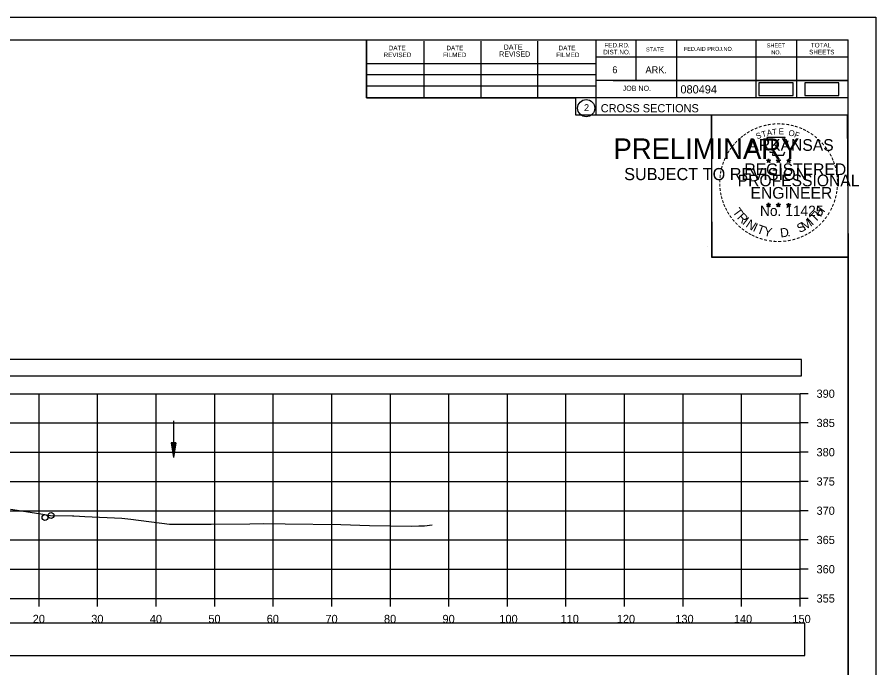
# Model space of a CAD drawing. Extents: x 1376273 to 1384221, y 378927 to 384592.
# Drawn here: x 1378240.7 to 1378387.4, y 379787.3 to 379898.5 of the extents above; entities that cross this region are included whole.
import ezdxf

# ---------------------------------------------------------------- set-up
doc = ezdxf.new("R2010")
doc.units = 0
for name, color, linetype in [('R_Axis', 7, 'Continuous'), ('R_Axis Annot', 7, 'Continuous'), ('R_Border', 7, 'Continuous'), ('R_Border PE', 7, 'Continuous'), ('R_Border Prem', 7, 'Continuous'), ('R_Drive', 7, 'Continuous'), ('R_Exist Surface', 7, 'Continuous'), ('R_Grid', 7, 'Continuous'), ('R_No Plot', 7, 'Continuous'), ('R_Water', 7, 'Continuous')]:
    doc.layers.add(name, color=color, linetype=linetype)

msp = doc.modelspace()

# ---------------------------------------------------------------- linework, layer by layer
at = {"layer": 'R_Axis'}
for p, q in [((1378374.46, 379799.14), (1378374.46, 379834.14)), ((1378375.86, 379834.14), (1378374.46, 379834.14)), ((1378375.86, 379829.14), (1378374.46, 379829.14)), ((1378375.86, 379824.14), (1378374.46, 379824.14)), ((1378375.86, 379819.14), (1378374.46, 379819.14)), ((1378375.86, 379814.14), (1378374.46, 379814.14)), ((1378375.86, 379809.14), (1378374.46, 379809.14)), ((1378375.86, 379804.14), (1378374.46, 379804.14)), ((1378074.46, 379799.14), (1378374.46, 379799.14)), ((1378244.46, 379797.74), (1378244.46, 379799.14)), ((1378254.46, 379797.74), (1378254.46, 379799.14)), ((1378264.46, 379797.74), (1378264.46, 379799.14)), ((1378274.46, 379797.74), (1378274.46, 379799.14)), ((1378284.46, 379797.74), (1378284.46, 379799.14)), ((1378294.46, 379797.74), (1378294.46, 379799.14)), ((1378304.46, 379797.74), (1378304.46, 379799.14)), ((1378314.46, 379797.74), (1378314.46, 379799.14)), ((1378324.46, 379797.74), (1378324.46, 379799.14)), ((1378334.46, 379797.74), (1378334.46, 379799.14)), ((1378344.46, 379797.74), (1378344.46, 379799.14)), ((1378354.46, 379797.74), (1378354.46, 379799.14)), ((1378364.46, 379797.74), (1378364.46, 379799.14)), ((1378374.46, 379797.74), (1378374.46, 379799.14)), ((1378375.86, 379799.14), (1378374.46, 379799.14))]:
    msp.add_line(p, q, dxfattribs=at)
at = {"layer": 'R_Axis Annot'}
for points in [[(1378072.9, 379837.19), (1378374.7, 379837.19), (1378374.7, 379840.01), (1378072.9, 379840.01)], [(1378073.48, 379789.42), (1378375.28, 379789.42), (1378375.28, 379794.94), (1378073.48, 379794.94)]]:
    msp.add_lwpolyline(points, close=True, dxfattribs=at)
at = {"layer": 'R_Border'}
for p, q in [((1378066.46, 379894.6), (1378382.64, 379894.6)), ((1378300.38, 379884.72), (1378300.38, 379894.6)), ((1378310.24, 379884.72), (1378310.24, 379894.4)), ((1378320, 379884.72), (1378320, 379894.4)), ((1378329.68, 379884.72), (1378329.68, 379894.4)), ((1378339.54, 379894.6), (1378339.54, 379881.8)), ((1378346.38, 379894.6), (1378346.38, 379887.66)), ((1378353.32, 379894.6), (1378353.32, 379884.72)), ((1378366.9, 379894.6), (1378366.9, 379884.72)), ((1378373.84, 379894.6), (1378373.84, 379884.72)), ((1378382.64, 379689.14), (1378382.64, 379894.6)), ((1378382.64, 379891.66), (1378339.54, 379891.66)), ((1378382.64, 379891.68), (1378382.64, 379891.68)), ((1378300.38, 379890.58), (1378339.54, 379890.58)), ((1378300.38, 379888.72), (1378339.54, 379888.72)), ((1378300.38, 379884.72), (1378300.38, 379886.78)), ((1378300.38, 379886.78), (1378339.54, 379886.78)), ((1378382.64, 379887.66), (1378339.54, 379887.66)), ((1378342.5, 379887.66), (1378382.64, 379887.66)), ((1378382.64, 379884.72), (1378300.38, 379884.72)), ((1378339.54, 379881.8), (1378382.64, 379881.8))]:
    msp.add_line(p, q, dxfattribs=at)
msp.add_circle((1378337.92, 379882.94), 1.47, dxfattribs=at)
at = {"layer": 'R_Border PE'}
for p, q in [((1378368.72, 379874.06), (1378369.07, 379873.95)), ((1378368.72, 379874.06), (1378368.98, 379874.01)), ((1378368.72, 379874.06), (1378368.96, 379873.94)), ((1378368.86, 379873.65), (1378369.07, 379873.95)), ((1378368.86, 379873.65), (1378368.98, 379873.89)), ((1378368.86, 379873.65), (1378369.07, 379873.87)), ((1378369.07, 379874.31), (1378369.03, 379874.06)), ((1378369.07, 379873.95), (1378369.07, 379874.31)), ((1378369.07, 379874.31), (1378369.12, 379874.06)), ((1378369.42, 379874.06), (1378369.07, 379873.95)), ((1378369.28, 379873.65), (1378369.07, 379873.95)), ((1378369.28, 379873.65), (1378369.07, 379873.86)), ((1378369.42, 379874.06), (1378369.13, 379874.01)), ((1378369.28, 379873.65), (1378369.15, 379873.94)), ((1378369.42, 379874.06), (1378369.21, 379873.96)), ((1378370.39, 379874.06), (1378370.74, 379873.95)), ((1378370.39, 379874.06), (1378370.65, 379874.01)), ((1378370.39, 379874.06), (1378370.63, 379873.94)), ((1378370.53, 379873.65), (1378370.74, 379873.95)), ((1378370.53, 379873.65), (1378370.65, 379873.89)), ((1378370.53, 379873.65), (1378370.74, 379873.87)), ((1378370.74, 379874.31), (1378370.7, 379874.06)), ((1378370.74, 379873.95), (1378370.74, 379874.31)), ((1378370.74, 379874.31), (1378370.79, 379874.06)), ((1378371.09, 379874.06), (1378370.74, 379873.95)), ((1378370.95, 379873.65), (1378370.74, 379873.95)), ((1378370.95, 379873.65), (1378370.74, 379873.86)), ((1378371.09, 379874.06), (1378370.8, 379874.01)), ((1378370.95, 379873.65), (1378370.82, 379873.94)), ((1378371.09, 379874.06), (1378370.88, 379873.96)), ((1378372.16, 379874.05), (1378372.51, 379873.93)), ((1378372.16, 379874.05), (1378372.41, 379874)), ((1378372.16, 379874.05), (1378372.39, 379873.92)), ((1378372.29, 379873.64), (1378372.51, 379873.93)), ((1378372.29, 379873.64), (1378372.42, 379873.88)), ((1378372.29, 379873.64), (1378372.5, 379873.85)), ((1378372.51, 379874.3), (1378372.46, 379874.05)), ((1378372.72, 379873.64), (1378372.5, 379873.85)), ((1378372.51, 379873.93), (1378372.51, 379874.3)), ((1378372.51, 379874.3), (1378372.55, 379874.05)), ((1378372.85, 379874.05), (1378372.51, 379873.93)), ((1378372.72, 379873.64), (1378372.51, 379873.93)), ((1378372.85, 379874.05), (1378372.57, 379874)), ((1378372.72, 379873.64), (1378372.58, 379873.93)), ((1378372.85, 379874.05), (1378372.65, 379873.94)), ((1378368.72, 379866.48), (1378369.07, 379866.37)), ((1378368.72, 379866.48), (1378368.97, 379866.44)), ((1378368.72, 379866.48), (1378368.96, 379866.36)), ((1378368.85, 379866.08), (1378369.07, 379866.37)), ((1378368.85, 379866.08), (1378368.98, 379866.32)), ((1378368.85, 379866.08), (1378369.07, 379866.29)), ((1378369.07, 379866.74), (1378369.03, 379866.49)), ((1378369.07, 379866.37), (1378369.07, 379866.74)), ((1378369.07, 379866.74), (1378369.12, 379866.49)), ((1378369.41, 379866.48), (1378369.07, 379866.37)), ((1378369.28, 379866.08), (1378369.07, 379866.37)), ((1378369.28, 379866.08), (1378369.07, 379866.29)), ((1378369.41, 379866.48), (1378369.13, 379866.44)), ((1378369.28, 379866.08), (1378369.14, 379866.37)), ((1378369.41, 379866.48), (1378369.21, 379866.38)), ((1378370.39, 379866.48), (1378370.74, 379866.37)), ((1378370.39, 379866.48), (1378370.64, 379866.44)), ((1378370.39, 379866.48), (1378370.62, 379866.36)), ((1378370.52, 379866.08), (1378370.74, 379866.37)), ((1378370.52, 379866.08), (1378370.65, 379866.32)), ((1378370.52, 379866.08), (1378370.73, 379866.29)), ((1378370.74, 379866.74), (1378370.7, 379866.49)), ((1378370.95, 379866.08), (1378370.73, 379866.29)), ((1378370.74, 379866.37), (1378370.74, 379866.74)), ((1378370.74, 379866.74), (1378370.79, 379866.49)), ((1378371.08, 379866.48), (1378370.74, 379866.37)), ((1378370.95, 379866.08), (1378370.74, 379866.37)), ((1378371.08, 379866.48), (1378370.8, 379866.44)), ((1378370.95, 379866.08), (1378370.81, 379866.37)), ((1378371.08, 379866.48), (1378370.88, 379866.38)), ((1378372.15, 379866.47), (1378372.5, 379866.36)), ((1378372.15, 379866.47), (1378372.41, 379866.43)), ((1378372.15, 379866.47), (1378372.39, 379866.35)), ((1378372.29, 379866.07), (1378372.5, 379866.36)), ((1378372.29, 379866.07), (1378372.41, 379866.31)), ((1378372.29, 379866.07), (1378372.5, 379866.28)), ((1378372.5, 379866.73), (1378372.46, 379866.48)), ((1378372.5, 379866.36), (1378372.5, 379866.73)), ((1378372.5, 379866.73), (1378372.55, 379866.48)), ((1378372.85, 379866.47), (1378372.5, 379866.36)), ((1378372.72, 379866.07), (1378372.5, 379866.36)), ((1378372.72, 379866.07), (1378372.5, 379866.28)), ((1378372.85, 379866.47), (1378372.56, 379866.43)), ((1378372.72, 379866.07), (1378372.58, 379866.36)), ((1378372.85, 379866.47), (1378372.65, 379866.37))]:
    msp.add_line(p, q, dxfattribs=at)
for points in [[(1378368.76, 379877.94), (1378369.03, 379877.11)], [(1378372.27, 379877.01), (1378372.42, 379877.3), (1378371.73, 379877.27), (1378371.88, 379877.94), (1378368.76, 379877.94)], [(1378369.26, 379875.51), (1378369.26, 379875.43), (1378369.82, 379875.41), (1378369.76, 379874.93), (1378371.63, 379874.93), (1378371.84, 379875.47)], [(1378369.07, 379874.31), (1378369.28, 379873.65), (1378368.72, 379874.06), (1378369.42, 379874.06), (1378368.86, 379873.65), (1378369.07, 379874.31)], [(1378370.74, 379874.31), (1378370.95, 379873.65), (1378370.39, 379874.06), (1378371.09, 379874.06), (1378370.53, 379873.65), (1378370.74, 379874.31)], [(1378372.51, 379874.3), (1378372.72, 379873.64), (1378372.16, 379874.05), (1378372.85, 379874.05), (1378372.29, 379873.64), (1378372.51, 379874.3)], [(1378369.07, 379866.74), (1378369.28, 379866.08), (1378368.72, 379866.48), (1378369.41, 379866.48), (1378368.85, 379866.08), (1378369.07, 379866.74)], [(1378370.74, 379866.74), (1378370.95, 379866.08), (1378370.39, 379866.48), (1378371.08, 379866.48), (1378370.52, 379866.08), (1378370.74, 379866.74)], [(1378372.5, 379866.73), (1378372.72, 379866.07), (1378372.15, 379866.47), (1378372.85, 379866.47), (1378372.29, 379866.07), (1378372.5, 379866.73)]]:
    msp.add_lwpolyline(points, dxfattribs=at)
for centre, radius in [((1378369.07, 379873.95), 0.172), ((1378369.07, 379873.95), 0.145), ((1378369.07, 379873.95), 0.116), ((1378369.07, 379873.95), 0.0991), ((1378369.07, 379873.95), 0.0747), ((1378369.07, 379873.95), 0.0495), ((1378369.07, 379873.95), 0.0296), ((1378370.74, 379873.95), 0.172), ((1378370.74, 379873.95), 0.145), ((1378370.74, 379873.95), 0.116), ((1378370.74, 379873.95), 0.0991), ((1378370.74, 379873.95), 0.0747), ((1378370.74, 379873.95), 0.0495), ((1378370.74, 379873.95), 0.0296), ((1378372.5, 379873.93), 0.172), ((1378372.5, 379873.93), 0.145), ((1378372.5, 379873.93), 0.116), ((1378372.5, 379873.93), 0.0991), ((1378372.5, 379873.93), 0.0747), ((1378372.5, 379873.93), 0.0495), ((1378372.5, 379873.93), 0.0296), ((1378369.07, 379866.37), 0.172), ((1378369.07, 379866.37), 0.145), ((1378369.07, 379866.37), 0.116), ((1378369.07, 379866.37), 0.0991), ((1378369.07, 379866.37), 0.0747), ((1378369.07, 379866.37), 0.0495), ((1378369.07, 379866.37), 0.0296), ((1378370.74, 379866.37), 0.172), ((1378370.74, 379866.37), 0.145), ((1378370.74, 379866.37), 0.116), ((1378370.74, 379866.37), 0.0991), ((1378370.74, 379866.37), 0.0747), ((1378370.74, 379866.37), 0.0495), ((1378370.74, 379866.37), 0.0296), ((1378372.5, 379866.36), 0.172), ((1378372.5, 379866.36), 0.145), ((1378372.5, 379866.36), 0.116), ((1378372.5, 379866.36), 0.0991), ((1378372.5, 379866.36), 0.0747), ((1378372.5, 379866.36), 0.0495), ((1378372.5, 379866.36), 0.0296)]:
    msp.add_circle(centre, radius, dxfattribs=at)
at = {"layer": 'R_Drive'}
for points in [[(1378367.43, 379885.08), (1378373.26, 379885.08), (1378373.26, 379887.27), (1378367.43, 379887.27)], [(1378375.24, 379885.1), (1378381.08, 379885.1), (1378381.08, 379887.29), (1378375.24, 379887.29)]]:
    msp.add_lwpolyline(points, close=True, dxfattribs=at)
at = {"layer": 'R_Exist Surface'}
msp.add_lwpolyline([(1378239.55, 379814.42), (1378244.42, 379813.65), (1378246.4, 379813.33), (1378250.14, 379813.26), (1378250.38, 379813.25), (1378251.38, 379813.2), (1378252.25, 379813.15), (1378258.57, 379812.84), (1378260.12, 379812.67), (1378266.72, 379811.83), (1378273.84, 379811.86), (1378280.48, 379811.87), (1378282.8, 379811.93), (1378286.49, 379811.87), (1378296.02, 379811.78), (1378300.88, 379811.63), (1378308.15, 379811.5), (1378309.32, 379811.55), (1378310.27, 379811.55), (1378311.61, 379811.73)], dxfattribs=at)
at = {"layer": 'R_Grid'}
for p, q in [((1378074.46, 379834.14), (1378374.46, 379834.14)), ((1378244.46, 379799.14), (1378244.46, 379834.14)), ((1378254.46, 379799.14), (1378254.46, 379834.14)), ((1378264.46, 379799.14), (1378264.46, 379834.14)), ((1378274.46, 379799.14), (1378274.46, 379834.14)), ((1378284.46, 379799.14), (1378284.46, 379834.14)), ((1378294.46, 379799.14), (1378294.46, 379834.14)), ((1378304.46, 379799.14), (1378304.46, 379834.14)), ((1378314.46, 379799.14), (1378314.46, 379834.14)), ((1378324.46, 379799.14), (1378324.46, 379834.14)), ((1378334.46, 379799.14), (1378334.46, 379834.14)), ((1378344.46, 379799.14), (1378344.46, 379834.14)), ((1378354.46, 379799.14), (1378354.46, 379834.14)), ((1378364.46, 379799.14), (1378364.46, 379834.14)), ((1378374.46, 379799.14), (1378374.46, 379834.14)), ((1378074.46, 379829.14), (1378374.46, 379829.14)), ((1378074.46, 379824.14), (1378374.46, 379824.14)), ((1378074.46, 379819.14), (1378374.46, 379819.14)), ((1378074.46, 379814.14), (1378374.46, 379814.14)), ((1378074.46, 379809.14), (1378374.46, 379809.14)), ((1378074.46, 379804.14), (1378374.46, 379804.14)), ((1378074.46, 379799.14), (1378374.46, 379799.14))]:
    msp.add_line(p, q, dxfattribs=at)
at = {"layer": 'R_No Plot'}
for p, q in [((1378054.06, 379898.5), (1378387.39, 379898.5)), ((1378358.67, 379859.35), (1378358.67, 379859.35))]:
    msp.add_line(p, q, dxfattribs=at)
for points in [[(1378054.05, 379898.5), (1378387.39, 379898.5), (1378387.39, 379685.16), (1378054.05, 379685.16)], [(1378300.38, 379894.6), (1378300.38, 379884.72), (1378336.11, 379884.72), (1378336.11, 379881.8), (1378359.31, 379881.8), (1378359.31, 379857.47), (1378382.64, 379857.47), (1378382.64, 379689.14), (1378066.46, 379689.14), (1378066.46, 379894.6)], [(1378359.31, 379881.8), (1378382.52, 379881.8), (1378382.64, 379857.47), (1378359.43, 379857.47)]]:
    msp.add_lwpolyline(points, close=True, dxfattribs=at)
for centre in [(1378245.46, 379812.98), (1378246.5, 379813.33)]:
    msp.add_circle(centre, 0.5, dxfattribs=at)
at = {"layer": 'R_Water'}
for p, q in [((1378267.41, 379829.48), (1378267.41, 379823.23)), ((1378267.04, 379825.73), (1378267.41, 379823.23)), ((1378267.79, 379825.73), (1378267.04, 379825.73)), ((1378267.1, 379825.73), (1378267.41, 379823.65)), ((1378267.16, 379825.73), (1378267.41, 379824.08)), ((1378267.22, 379825.73), (1378267.41, 379824.5)), ((1378267.29, 379825.73), (1378267.41, 379824.92)), ((1378267.35, 379825.73), (1378267.41, 379825.34)), ((1378267.79, 379825.73), (1378267.41, 379823.23)), ((1378267.53, 379825.73), (1378267.41, 379824.92)), ((1378267.66, 379825.73), (1378267.41, 379824.08)), ((1378267.72, 379825.73), (1378267.41, 379823.65)), ((1378267.6, 379825.73), (1378267.41, 379824.5)), ((1378267.47, 379825.73), (1378267.41, 379825.34))]:
    msp.add_line(p, q, dxfattribs=at)

# ---------------------------------------------------------------- texts
at = {"layer": 'R_Axis Annot'}
for s, p in [('390', (1378377.26, 379833.44)), ('385', (1378377.26, 379828.44)), ('380', (1378377.26, 379823.44)), ('375', (1378377.26, 379818.44)), ('370', (1378377.26, 379813.44)), ('365', (1378377.26, 379808.44)), ('360', (1378377.26, 379803.44)), ('355', (1378377.26, 379798.44)), ('20', (1378243.37, 379794.94)), ('30', (1378253.37, 379794.94)), ('40', (1378263.37, 379794.94)), ('50', (1378273.37, 379794.94)), ('60', (1378283.34, 379794.94)), ('70', (1378293.37, 379794.94)), ('80', (1378303.37, 379794.94)), ('90', (1378313.37, 379794.94)), ('100', (1378323.08, 379794.94)), ('110', (1378333.54, 379794.94)), ('120', (1378343.14, 379794.94)), ('130', (1378353.14, 379794.94)), ('140', (1378363.14, 379794.94)), ('150', (1378373.14, 379794.94))]:
    msp.add_text(s, height=1.4, dxfattribs=at).set_placement(p)
at = {"layer": 'R_Border'}
for s, height, p in [('FED.RD.', 0.782, (1378341.02, 379893.32)), ('SHEET', 0.684, (1378368.76, 379893.32)), ('TOTAL', 0.782, (1378376.28, 379893.32)), ('DATE', 0.782, (1378304.18, 379892.84)), ('DATE', 0.782, (1378314.04, 379892.84)), ('REVISED', 0.879, (1378323.04, 379891.76)), ('DATE', 0.879, (1378323.82, 379892.94)), ('DATE', 0.782, (1378333.2, 379892.84)), ('DIST.NO.', 0.782, (1378340.82, 379892.14)), ('STATE', 0.684, (1378348.14, 379892.64)), ('FED.AID PROJ.NO.', 0.684, (1378354.6, 379892.74)), ('NO.', 0.684, (1378369.54, 379892.14)), ('SHEETS', 0.782, (1378376, 379892.14)), ('REVISED', 0.782, (1378303.3, 379891.66)), ('FILMED', 0.782, (1378313.46, 379891.66)), ('FILMED', 0.782, (1378332.8, 379891.66)), ('6', 1.17, (1378342.38, 379888.92)), ('ARK.', 1.172, (1378348.04, 379888.92)), ('JOB NO.', 0.879, (1378344.14, 379885.9)), ('080494', 1.4, (1378354.01, 379885.46)), ('2', 1.17, (1378337.54, 379882.45)), ('CROSS SECTIONS', 1.4, (1378340.4, 379882.23))]:
    msp.add_text(s, height=height, rotation=360, dxfattribs=at).set_placement(p)
at = {"layer": 'R_Border PE'}
for s, height, rotation, p in [('-', 1.6, 28.7918, (1378366.24, 379878.48)), ('-', 1.6, 24.3072, (1378366.88, 379878.79)), ('-', 1.6, 19.1761, (1378367.51, 379879.06)), ('-', 1.6, 13.6301, (1378368.26, 379879.3)), ('-', 1.6, 10.2193, (1378368.94, 379879.47)), ('T', 1, 6.0228, (1378369.71, 379878.36)), ('-', 1.6, 5.8968, (1378369.67, 379879.58)), ('-', 1.6, 0.1862, (1378370.44, 379879.65)), ('E', 1, 0.8323, (1378370.81, 379878.47)), ('-', 1.6, 357.743, (1378371.16, 379879.63)), ('-', 1.6, 352.1617, (1378371.91, 379879.58)), ('-', 1.6, 347.2049, (1378372.63, 379879.46)), ('-', 1.6, 342.3362, (1378373.26, 379879.31)), ('-', 1.6, 337.8551, (1378374, 379879.09)), ('-', 1.6, 334.1211, (1378374.63, 379878.82)), ('-', 1.6, 38.9507, (1378364.59, 379877.33)), ('-', 1.6, 36.2317, (1378365.07, 379877.71)), ('-', 1.6, 34.0636, (1378365.65, 379878.11)), ('S', 1, 21.594, (1378367.12, 379877.61)), ('T', 1, 16.4036, (1378368.03, 379877.94)), ('A', 1, 11.2132, (1378368.86, 379878.2)), ('O', 1, 350.4515, (1378372.42, 379878.26)), ('F', 1, 340.0707, (1378373.37, 379878.03)), ('-', 1.6, 329.6409, (1378375.21, 379878.53)), ('-', 1.6, 325.8627, (1378375.85, 379878.17)), ('-', 1.6, 320.5297, (1378376.46, 379877.75)), ('-', 1.6, 50.6142, (1378363.31, 379875.95)), ('-', 1.6, 48.423, (1378363.71, 379876.44)), ('-', 1.6, 42.9622, (1378364.16, 379876.92)), ('ARKANSAS', 2, 360, (1378365.62, 379875.65)), ('-', 1.6, 315.5786, (1378377.06, 379877.26)), ('-', 1.6, 309.8797, (1378377.63, 379876.71)), ('-', 1.6, 306.6522, (1378378.15, 379876.11)), ('-', 1.6, 62.8713, (1378362.26, 379874.24)), ('-', 1.6, 58.0706, (1378362.57, 379874.86)), ('-', 1.6, 54.2325, (1378362.9, 379875.39)), ('-', 1.4, 303.6753, (1378378.64, 379875.54)), ('-', 1.6, 299.6684, (1378378.96, 379874.93)), ('-', 1.6, 72.3945, (1378361.78, 379873)), ('-', 1.6, 67.7743, (1378362, 379873.63)), ('REGISTERED', 2, 360, (1378364.94, 379871.5)), ('DWB', 0.01, 360, (1378369.06, 379873.94)), ('DWB', 0.01, 360, (1378370.73, 379873.94)), ('DWB', 0.01, 360, (1378372.49, 379873.93)), ('-', 1.6, 294.6628, (1378379.28, 379874.32)), ('-', 1.6, 290.5728, (1378379.54, 379873.74)), ('-', 1.6, 81.2013, (1378361.45, 379871.58)), ('-', 1.6, 75.461, (1378361.58, 379872.29)), ('-', 1.6, 285.1233, (1378379.77, 379873.16)), ('-', 1.6, 280.5493, (1378379.97, 379872.42)), ('-', 1.6, 89.0622, (1378361.35, 379870.18)), ('-', 1.6, 85.1863, (1378361.37, 379870.89)), ('PROFESSIONAL', 2, 360, (1378363.79, 379869.59)), ('-', 1.6, 276.5962, (1378380.13, 379871.65)), ('-', 1.6, 274.3301, (1378380.19, 379870.93)), ('-', 1.6, 94.1959, (1378361.38, 379869.46)), ('-', 1.6, 98.9479, (1378361.46, 379868.79)), ('ENGINEER', 2, 360, (1378365.98, 379867.47)), ('-', 1.6, 263.5172, (1378380.21, 379869.63)), ('-', 1.6, 269.9407, (1378380.23, 379870.3)), ('-', 1.6, 101.7149, (1378361.59, 379868.06)), ('-', 1.6, 105.4578, (1378361.75, 379867.46)), ('-', 1.6, 255.7626, (1378380.03, 379868.3)), ('-', 1.6, 260.9953, (1378380.14, 379868.98)), ('-', 1.6, 109.0874, (1378361.97, 379866.83)), ('-', 1.6, 114.0643, (1378362.22, 379866.24)), ('No. 11425', 1.757, 360, (1378367.6, 379864.52)), ('DWB', 0.01, 360, (1378369.05, 379866.37)), ('DWB', 0.01, 360, (1378370.72, 379866.37)), ('DWB', 0.01, 360, (1378372.49, 379866.36)), ('H', 1.54, 54.6088, (1378377.95, 379864.25)), ('-', 1.6, 247.8887, (1378379.62, 379866.91)), ('-', 1.6, 252.8681, (1378379.85, 379867.58)), ('-', 1.6, 115.7289, (1378362.53, 379865.62)), ('-', 1.6, 120.4471, (1378362.88, 379865.03)), ('-', 1.6, 125.8934, (1378363.29, 379864.47)), ('T', 1.54, 306.0406, (1378362.83, 379865.21)), ('R', 1.54, 314.005, (1378363.59, 379864.16)), ('T', 1.54, 46.6444, (1378377.06, 379863.3)), ('-', 1.6, 239.0712, (1378378.97, 379865.53)), ('-', 1.6, 244.6197, (1378379.36, 379866.28)), ('-', 1.6, 130.7181, (1378363.75, 379863.92)), ('-', 1.6, 134.2238, (1378364.27, 379863.38)), ('I', 1.54, 321.9694, (1378364.49, 379863.23)), ('N', 1.54, 326.5002, (1378365.06, 379862.76)), ('I', 1.54, 335.3603, (1378366.26, 379861.97)), ('S', 1.54, 26.9312, (1378374.37, 379861.57)), ('M', 1.54, 32.6563, (1378375.21, 379861.98)), ('I', 1.54, 42.1136, (1378376.5, 379862.83)), ('-', 1.6, 225.7653, (1378377.66, 379863.74)), ('-', 1.6, 231.2538, (1378378.14, 379864.31)), ('-', 1.6, 233.8452, (1378378.57, 379864.87)), ('-', 1.6, 138.9338, (1378364.79, 379862.91)), ('-', 1.6, 144.6463, (1378365.35, 379862.51)), ('-', 1.6, 148.0898, (1378365.91, 379862.13)), ('T', 1.54, 339.8912, (1378366.93, 379861.65)), ('Y', 1.54, 347.8556, (1378368.14, 379861.2)), ('D', 1.54, 6.3969, (1378371.13, 379860.84)), ('-', 1.6, 212.2491, (1378376.05, 379862.37)), ('-', 1.6, 215.7363, (1378376.59, 379862.76)), ('-', 1.6, 221.0851, (1378377.13, 379863.23)), ('-', 1.6, 151.5704, (1378366.49, 379861.81)), ('-', 1.6, 154.6002, (1378367.01, 379861.56)), ('-', 1.6, 158.5612, (1378367.63, 379861.31)), ('-', 1.6, 162.7983, (1378368.32, 379861.1)), ('-', 1.6, 167.5555, (1378369.04, 379860.93)), ('-', 1.6, 173.1155, (1378369.81, 379860.82)), ('-', 1.6, 176.5183, (1378370.56, 379860.77)), ('-', 1.6, 181.5918, (1378371.3, 379860.79)), ('-', 1.6, 185.8167, (1378372.11, 379860.86)), ('-', 1.6, 191.2858, (1378372.84, 379861)), ('.', 1.54, 13.7642, (1378372.32, 379860.97)), ('-', 1.6, 195.4743, (1378373.57, 379861.19)), ('-', 1.6, 200.7184, (1378374.25, 379861.44)), ('-', 1.6, 204.2516, (1378374.87, 379861.71)), ('-', 1.6, 207.3568, (1378375.49, 379862.03))]:
    msp.add_text(s, height=height, rotation=rotation, dxfattribs=at).set_placement(p)
at = {"layer": 'R_Border Prem'}
for s, height, p in [('PRELIMINARY', 3.5, (1378342.59, 379874.27)), ('DWB', 0.01, (1378343.33, 379876.11)), ('SUBJECT TO REVISION', 2.0751, (1378344.4, 379870.64))]:
    msp.add_text(s, height=height, rotation=360, dxfattribs=at).set_placement(p)

doc.saveas('drawing.dxf')
